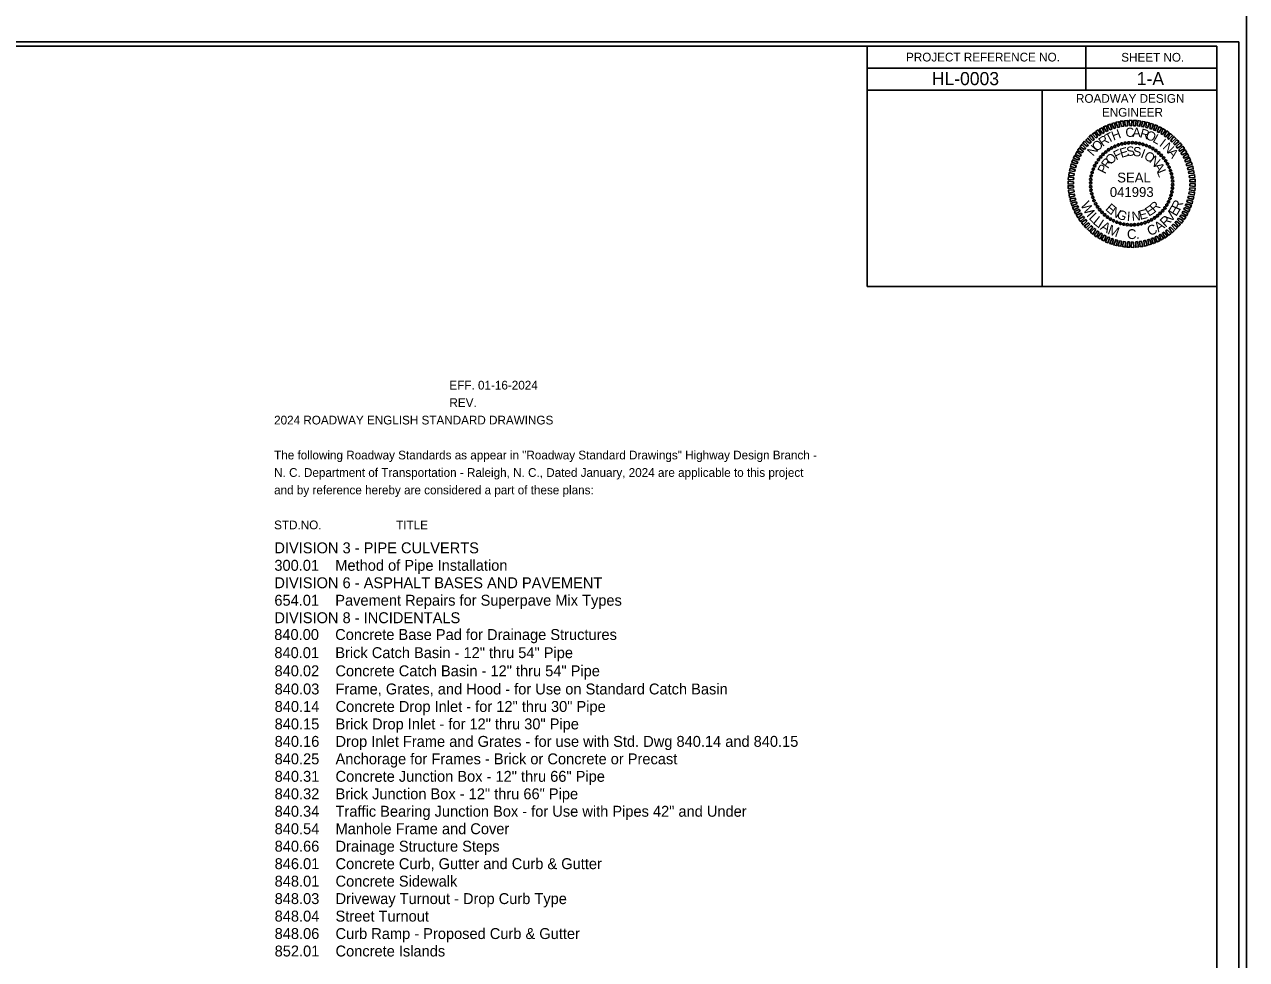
# Model space of a CAD drawing. Extents: x 925297 to 940193, y 663541 to 689899.
# Drawn here: x 933170 to 938765, y 676737 to 681019 of the extents above; entities that cross this region are included whole.
import ezdxf

# ---------------------------------------------------------------- set-up
doc = ezdxf.new("R2010")
doc.units = 0
for name, color, linetype in [('Default', 7, 'Continuous'), ('Sheet Data Field CELL', 7, 'Continuous'), ('Sheet Plan CELL', 7, 'Continuous'), ('Sheet Plot Border Inside CELL', 7, 'Continuous'), ('Sheet Plot Border Outside CELL', 7, 'Continuous')]:
    doc.layers.add(name, color=color, linetype=linetype)

msp = doc.modelspace()

# ---------------------------------------------------------------- linework, layer by layer
at = {"layer": 'Default'}
for p, q in [((938147.3, 680453.4), (938147.3, 680453.4)), ((938162, 680460.9), (938162, 680460.9)), ((938177, 680466.9), (938177, 680466.9)), ((938192.7, 680471.4), (938192.7, 680471.4)), ((938209.2, 680474.4), (938209.2, 680474.4)), ((938225.3, 680476.6), (938225.3, 680476.6)), ((938241.8, 680477), (938241.8, 680477)), ((938258.3, 680475.9), (938258.3, 680475.9)), ((938274.5, 680473.2), (938274.5, 680473.2)), ((938290.2, 680469.9), (938290.2, 680469.9)), ((938306, 680464.6), (938306, 680464.6)), ((938321, 680457.9), (938321, 680457.9)), ((938086.2, 680399.4), (938086.2, 680399.4)), ((938096.3, 680412.5), (938096.3, 680412.5)), ((938107.6, 680424.1), (938107.6, 680424.1)), ((938120, 680435.4), (938120, 680435.4)), ((938133.1, 680444.7), (938133.1, 680444.7)), ((938335.6, 680450.4), (938335.6, 680450.4)), ((938349.1, 680441), (938349.1, 680441)), ((938362.2, 680430.9), (938362.2, 680430.9)), ((938373.8, 680419.6), (938373.8, 680419.6)), ((938385.1, 680407.2), (938385.1, 680407.2)), ((938062.6, 680356.2), (938062.6, 680356.2)), ((938069.3, 680371.2), (938069.3, 680371.2)), ((938076.8, 680385.9), (938076.8, 680385.9)), ((938394.5, 680394.1), (938394.5, 680394.1)), ((938403.1, 680379.9), (938403.1, 680379.9)), ((938410.6, 680365.2), (938410.6, 680365.2)), ((938416.6, 680350.2), (938416.6, 680350.2)), ((938050.2, 680292.1), (938050.2, 680292.1)), ((938051.3, 680308.6), (938051.3, 680308.6)), ((938054, 680324.7), (938054, 680324.7)), ((938057.3, 680340.5), (938057.3, 680340.5)), ((938238.5, 680288.7), (938238.5, 680288.7)), ((938421.1, 680334.5), (938421.1, 680334.5)), ((938424.1, 680318), (938424.1, 680318)), ((938426.3, 680301.9), (938426.3, 680301.9)), ((938426.7, 680285.4), (938426.7, 680285.4)), ((938050.6, 680275.6), (938050.6, 680275.6)), ((938052.8, 680259.5), (938052.8, 680259.5)), ((938055.8, 680243), (938055.8, 680243)), ((938419.6, 680237), (938419.6, 680237)), ((938423, 680252.7), (938423, 680252.7)), ((938425.6, 680268.9), (938425.6, 680268.9)), ((938060.3, 680227.2), (938060.3, 680227.2)), ((938066.3, 680212.2), (938066.3, 680212.2)), ((938073.8, 680197.6), (938073.8, 680197.6)), ((938082.5, 680183.4), (938082.5, 680183.4)), ((938390.7, 680178.1), (938390.7, 680178.1)), ((938400.1, 680191.6), (938400.1, 680191.6)), ((938407.6, 680206.2), (938407.6, 680206.2)), ((938414.3, 680221.2), (938414.3, 680221.2)), ((938091.8, 680170.2), (938091.8, 680170.2)), ((938103.1, 680157.9), (938103.1, 680157.9)), ((938114.7, 680146.6), (938114.7, 680146.6)), ((938127.8, 680136.5), (938127.8, 680136.5)), ((938141.3, 680127.1), (938141.3, 680127.1)), ((938156, 680119.6), (938156, 680119.6)), ((938329.6, 680124.1), (938329.6, 680124.1)), ((938343.8, 680132.7), (938343.8, 680132.7)), ((938357, 680142.1), (938357, 680142.1)), ((938369.3, 680153.4), (938369.3, 680153.4)), ((938380.6, 680165), (938380.6, 680165)), ((938171, 680112.9), (938171, 680112.9)), ((938186.7, 680107.6), (938186.7, 680107.6)), ((938202.5, 680104.2), (938202.5, 680104.2)), ((938218.6, 680101.6), (938218.6, 680101.6)), ((938235.1, 680100.5), (938235.1, 680100.5)), ((938251.6, 680100.9), (938251.6, 680100.9)), ((938267.7, 680103.1), (938267.7, 680103.1)), ((938284.2, 680106.1), (938284.2, 680106.1)), ((938300, 680110.6), (938300, 680110.6)), ((938315, 680116.6), (938315, 680116.6))]:
    msp.add_line(p, q, dxfattribs=at)
for points in [[(938156.7, 680542.2), (938148.1, 680564.7), (938159.7, 680568.1), (938164.6, 680544.9)], [(938174.7, 680547.1), (938166.8, 680570.7), (938179.6, 680573.4), (938182.6, 680549)], [(938192.7, 680551.2), (938186.7, 680575.2), (938199.1, 680576.4), (938201.7, 680552.4)], [(938210.7, 680553.5), (938206.6, 680577.5), (938219.3, 680579), (938219.7, 680554.6)], [(938229.5, 680555.4), (938227.6, 680579.7), (938240, 680579.4), (938238.5, 680555)], [(938247.5, 680555), (938247.5, 680579.4), (938259.8, 680579), (938256.5, 680554.6)], [(938266.2, 680553.9), (938267.7, 680578.2), (938280.1, 680576), (938275.2, 680552.4)], [(938284.2, 680550.9), (938287.6, 680574.9), (938300, 680573), (938293.2, 680549.7)], [(938303.3, 680546.7), (938307.1, 680571.1), (938319.8, 680568.1), (938311.2, 680544.9)], [(938321.3, 680541.9), (938327, 680565.1), (938338.6, 680561.4), (938329.2, 680539.2)], [(938060, 680487.1), (938043.5, 680503.6), (938052.5, 680512.6), (938067.1, 680492.4)], [(938075, 680498.7), (938058.8, 680516.7), (938069, 680524.6), (938082.1, 680503.6)], [(938089.2, 680510), (938075.3, 680529.1), (938085.1, 680536.2), (938097.5, 680514.5)], [(938105.7, 680519.4), (938091.8, 680539.6), (938103.5, 680545.6), (938112.8, 680523.9)], [(938121.8, 680528.4), (938109.8, 680549.4), (938121.5, 680554.6), (938130.1, 680531.7)], [(938138.3, 680536.2), (938128.6, 680558), (938139.8, 680562.5), (938147.7, 680538.5)], [(938338.2, 680535.1), (938346.8, 680558.7), (938357.3, 680554.2), (938346.8, 680532.5)], [(938355.1, 680528), (938364.5, 680550.1), (938376.1, 680544.9), (938363.3, 680523.9)], [(938372.3, 680519.4), (938382.5, 680540.7), (938393.7, 680534.4), (938379.5, 680514.9)], [(938387, 680509.2), (938400.1, 680531), (938409.8, 680523.1), (938395.2, 680504.7)], [(938402.3, 680498), (938416.2, 680518.6), (938426, 680510.4), (938409.5, 680492.7)], [(938023.2, 680445.5), (938003, 680458.2), (938010.1, 680469.1), (938028.1, 680452.6)], [(938034.5, 680459.7), (938015, 680474.4), (938023.2, 680484.1), (938039.7, 680466.5)], [(938047.6, 680474), (938028.5, 680489.4), (938037.8, 680498), (938053.6, 680480)], [(938416.6, 680486.4), (938432, 680505.9), (938441, 680496.9), (938423.7, 680480.7)], [(938430.1, 680473.2), (938446.2, 680490.9), (938455.2, 680481.9), (938435.7, 680467.2)], [(938443.2, 680459.7), (938460.5, 680476.6), (938468.3, 680466.5), (938448.5, 680452.2)], [(938454.5, 680445.1), (938472.8, 680460.9), (938480, 680450), (938459, 680438)], [(937988, 680380.6), (937964.7, 680387.4), (937969.6, 680399), (937992.1, 680388.5)], [(937995.5, 680397.1), (937972.2, 680405.7), (937977.8, 680417.4), (937999.2, 680405.4)], [(938003, 680414.4), (937981.6, 680423.7), (937987.2, 680435.4), (938007.5, 680421.5)], [(938012, 680430.5), (937991, 680441.7), (937998.5, 680452.2), (938018, 680437.2)], [(938464.2, 680429.7), (938484.1, 680444), (938491.2, 680432.7), (938469.5, 680422.2)], [(938474, 680413.2), (938495, 680426.4), (938499.8, 680414.7), (938478.5, 680406.1)], [(938481.5, 680397.1), (938503.6, 680408.4), (938508.5, 680396.4), (938485.2, 680388.9)], [(937977.5, 680344.6), (937954.2, 680347.6), (937956.8, 680360.4), (937980.5, 680352.5)], [(937982.3, 680362.6), (937959.1, 680367.5), (937961.7, 680379.9), (937985.3, 680370.5)], [(938488.2, 680379.5), (938511.1, 680389.2), (938515.2, 680377.6), (938492, 680371.6)], [(938494.2, 680361.5), (938518.2, 680370.1), (938520.5, 680357.7), (938496.8, 680353.6)], [(938498.7, 680343.5), (938522.3, 680350.6), (938524.6, 680337.9), (938501, 680335.6)], [(937972.2, 680288.7), (937947.8, 680287.6), (937947.8, 680300.4), (937972.2, 680297.7)], [(937972.6, 680307.5), (937948.2, 680308.2), (937949, 680320.6), (937973.3, 680316.5)], [(937974.5, 680325.5), (937950.5, 680327.7), (937952, 680340.5), (937976.3, 680334.5)], [(938502.1, 680325.5), (938526.5, 680330.7), (938527.6, 680318), (938503.6, 680316.5)], [(938504.3, 680307.5), (938528.7, 680310.5), (938529.5, 680297.7), (938505.1, 680298.5)], [(938504.7, 680288.7), (938529.1, 680289.9), (938529.1, 680277.1), (938504.7, 680279.7)], [(937972.6, 680270), (937948.2, 680267), (937947.5, 680279.7), (937971.8, 680279)], [(937974.8, 680252), (937950.5, 680246.7), (937949.3, 680259.5), (937973.3, 680261)], [(937978.2, 680234), (937954.6, 680226.9), (937952.3, 680239.6), (937976, 680241.9)], [(938499.5, 680232.9), (938522.7, 680229.9), (938520.1, 680217.1), (938496.5, 680225)], [(938502.5, 680252), (938526.5, 680249.7), (938525, 680237), (938500.6, 680243)], [(938504.3, 680270), (938528.7, 680269.2), (938528, 680256.9), (938503.6, 680261)], [(937982.7, 680216), (937958.7, 680207.4), (937956.5, 680219.7), (937980.1, 680223.9)], [(937988.7, 680198), (937965.8, 680188.2), (937961.7, 680199.9), (937985, 680205.9)], [(937995.5, 680180.4), (937973.3, 680169.1), (937968.5, 680181.1), (937991.7, 680188.6)], [(938481.5, 680180.4), (938504.7, 680171.7), (938499.1, 680160.1), (938477.7, 680172.1)], [(938489, 680196.9), (938512.2, 680190.1), (938507.3, 680178.5), (938484.8, 680189)], [(938494.6, 680214.9), (938517.8, 680210), (938515.2, 680197.6), (938491.6, 680207)], [(938003, 680164.2), (937982, 680151.1), (937977.1, 680162.7), (937998.5, 680171.4)], [(938012.7, 680147.7), (937992.8, 680133.5), (937985.7, 680144.7), (938007.5, 680155.2)], [(938022.5, 680132.4), (938004.1, 680116.6), (937997, 680127.5), (938018, 680139.5)], [(938033.7, 680117.7), (938016.5, 680100.9), (938008.6, 680111), (938028.5, 680125.2)], [(938442.5, 680117.7), (938462, 680103.1), (938453.7, 680093.4), (938437.2, 680111)], [(938453.7, 680132), (938474, 680119.2), (938466.8, 680108.4), (938448.8, 680124.9)], [(938465, 680147), (938486, 680135.7), (938478.5, 680125.2), (938459, 680140.2)], [(938474, 680163.1), (938495.3, 680153.7), (938489.7, 680142.1), (938469.5, 680156)], [(938046.8, 680104.2), (938030.7, 680086.6), (938021.7, 680095.6), (938041.2, 680110.2)], [(938060.3, 680091.1), (938045, 680071.6), (938036, 680080.6), (938053.2, 680096.7)], [(938074.6, 680079.5), (938060.7, 680058.9), (938051, 680067.1), (938067.5, 680084.7)], [(938090, 680068.2), (938076.8, 680046.5), (938067.1, 680054.4), (938081.7, 680072.7)], [(938104.6, 680058.1), (938094.5, 680036.7), (938083.2, 680043.1), (938097.5, 680062.6)], [(938387.7, 680067.5), (938401.6, 680048.4), (938391.8, 680041.2), (938379.5, 680063)], [(938402, 680078.7), (938418.1, 680060.7), (938408, 680052.9), (938394.8, 680073.9)], [(938417, 680090.4), (938433.5, 680073.9), (938424.5, 680064.9), (938409.8, 680085.1)], [(938429.3, 680103.5), (938448.5, 680088.1), (938439.1, 680079.5), (938423.3, 680097.5)], [(938121.8, 680049.5), (938112.5, 680027.4), (938100.8, 680032.6), (938113.6, 680053.6)], [(938138.7, 680042.4), (938130.1, 680018.7), (938119.6, 680023.2), (938130.1, 680045)], [(938155.6, 680035.6), (938150, 680012.4), (938138.3, 680016.1), (938147.7, 680038.2)], [(938173.6, 680030.7), (938169.8, 680006.4), (938157.1, 680009.4), (938165.7, 680032.6)], [(938192.7, 680026.6), (938189.3, 680002.6), (938177, 680004.5), (938183.7, 680027.7)], [(938210.7, 680023.6), (938209.2, 679999.2), (938196.8, 680001.5), (938201.7, 680025.1)], [(938229.5, 680022.5), (938229.5, 679998.1), (938217.1, 679998.5), (938220.5, 680022.9)], [(938247.5, 680022.1), (938249.3, 679997.7), (938237, 679998.1), (938238.5, 680022.5)], [(938266.2, 680024), (938270.3, 680000), (938257.6, 679998.5), (938257.2, 680022.9)], [(938284.2, 680026.2), (938290.2, 680002.2), (938277.8, 680001.1), (938275.2, 680025.1)], [(938302.2, 680030.4), (938310.1, 680006.7), (938297.3, 680004.1), (938294.3, 680028.5)], [(938320.2, 680035.2), (938328.8, 680012.7), (938317.2, 680009.4), (938312.3, 680032.6)], [(938338.6, 680041.2), (938348.3, 680019.5), (938337.1, 680015), (938329.2, 680039)], [(938355.1, 680049.1), (938367.1, 680028.1), (938355.5, 680022.9), (938346.8, 680045.7)], [(938371.2, 680058.1), (938385.1, 680037.9), (938373.5, 680031.9), (938364.1, 680053.6)]]:
    msp.add_lwpolyline(points, close=True, dxfattribs=at)
for centre, major_axis in [((938147.3, 680453.3), (-2.62, 4.72)), ((938162, 680460.6), (-2.2, 4.93)), ((938177.2, 680466.6), (-1.76, 5.11)), ((938193, 680471.3), (-1.31, 5.24)), ((938209, 680474.5), (-0.84, 5.33)), ((938225.4, 680476.4), (-0.38, 5.39)), ((938241.8, 680476.8), (0.09, 5.4)), ((938258.1, 680475.8), (0.56, 5.37)), ((938274.4, 680473.4), (1.03, 5.3)), ((938290.3, 680469.6), (1.49, 5.19)), ((938305.9, 680464.3), (1.94, 5.04)), ((938320.9, 680457.8), (2.37, 4.85)), ((938335.4, 680450), (2.78, 4.63)), ((938086.3, 680399.3), (-4.37, 3.17)), ((938096.5, 680412.1), (-4.08, 3.54)), ((938107.8, 680424), (-3.75, 3.88)), ((938120.1, 680434.9), (-3.4, 4.2)), ((938133.3, 680444.7), (-3.02, 4.48)), ((938349, 680440.9), (3.17, 4.37)), ((938361.9, 680430.7), (3.54, 4.08)), ((938373.8, 680419.4), (3.88, 3.75)), ((938384.7, 680407.1), (4.2, 3.4)), ((938394.4, 680393.9), (4.48, 3.02)), ((938057.7, 680340.6), (-5.19, 1.49)), ((938062.9, 680356.1), (-5.04, 1.94)), ((938069.4, 680371.2), (-4.85, 2.37)), ((938077.2, 680385.6), (-4.63, 2.78)), ((938403, 680379.9), (4.72, 2.62)), ((938410.3, 680365.2), (4.93, 2.2)), ((938416.3, 680350), (5.11, 1.76)), ((938050.4, 680292), (-5.4, 0.09)), ((938051.4, 680308.4), (-5.37, 0.56)), ((938053.8, 680324.6), (-5.3, 1.03)), ((938421, 680334.2), (5.24, 1.31)), ((938424.3, 680318.2), (5.33, 0.84)), ((938426.1, 680301.9), (5.39, 0.38)), ((938426.5, 680285.5), (5.4, -0.09)), ((938050.8, 680275.6), (-5.39, -0.38)), ((938052.7, 680259.3), (-5.33, -0.84)), ((938056, 680243.2), (-5.24, -1.31)), ((938060.6, 680227.5), (-5.11, -1.76)), ((938419.3, 680236.9), (5.19, -1.49)), ((938423.1, 680252.8), (5.3, -1.03)), ((938425.5, 680269.1), (5.37, -0.56)), ((938066.6, 680212.2), (-4.93, -2.2)), ((938074, 680197.5), (-4.72, -2.62)), ((938082.5, 680183.6), (-4.48, -3.02)), ((938092.3, 680170.4), (-4.2, -3.4)), ((938390.6, 680178.2), (4.37, -3.17)), ((938399.7, 680191.9), (4.63, -2.78)), ((938407.5, 680206.3), (4.85, -2.37)), ((938414.1, 680221.3), (5.04, -1.94)), ((938103.2, 680158.1), (-3.88, -3.75)), ((938115.1, 680146.8), (-3.54, -4.08)), ((938127.9, 680136.6), (-3.17, -4.37)), ((938141.6, 680127.5), (-2.78, -4.63)), ((938156, 680119.7), (-2.37, -4.85)), ((938171.1, 680113.1), (-1.94, -5.04)), ((938299.7, 680110.9), (1.76, -5.11)), ((938315, 680116.9), (2.2, -4.93)), ((938329.7, 680124.2), (2.62, -4.72)), ((938343.7, 680132.8), (3.02, -4.48)), ((938356.8, 680142.6), (3.4, -4.2)), ((938369.1, 680153.4), (3.75, -3.88)), ((938380.4, 680165.3), (4.08, -3.54)), ((938186.6, 680107.9), (-1.49, -5.19)), ((938202.6, 680104.1), (-1.03, -5.3)), ((938218.8, 680101.7), (-0.56, -5.37)), ((938235.2, 680100.7), (-0.09, -5.4)), ((938251.6, 680101.1), (0.38, -5.39)), ((938267.9, 680103), (0.84, -5.33)), ((938284, 680106.2), (1.31, -5.24))]:
    msp.add_ellipse(centre, major_axis=major_axis, ratio=0.999708, dxfattribs=at)
at = {"layer": 'Sheet Plan CELL'}
for p, q in [((937028.3, 680918.7), (938628.7, 680918.7)), ((937028.3, 679818.3), (937028.3, 680918.7)), ((938028.7, 680918.3), (938028.7, 680718.3)), ((938628.7, 680918.7), (938628.7, 680718.3)), ((937028.3, 680818.3), (938628.7, 680818.3)), ((938628.7, 680718.3), (937028.3, 680718.3)), ((938628.7, 680718.3), (937028.3, 680718.3)), ((937828.7, 680718.3), (938628.7, 680718.3)), ((937828.7, 679818.3), (937828.7, 680718.3)), ((938628.7, 680718.3), (938628.7, 679818.3)), ((938628.7, 679818.3), (937028.3, 679818.3)), ((938628.7, 679818.3), (937028.3, 679818.3))]:
    msp.add_line(p, q, dxfattribs=at)
msp.add_lwpolyline([(938628.7, 680918.7), (926628.7, 680918.7), (926628.7, 672518.7), (938628.7, 672518.7)], close=True, dxfattribs=at)
at = {"layer": 'Sheet Plot Border Inside CELL'}
msp.add_lwpolyline([(925400.7, 672498.7), (938728.7, 672498.7), (938728.7, 680938.7), (925400.7, 680938.7)], close=True, dxfattribs=at)
at = {"layer": 'Sheet Plot Border Outside CELL'}
msp.add_lwpolyline([(925296.7, 672338.7), (938764.7, 672338.7), (938764.7, 681098.7), (925296.7, 681098.7)], close=True, dxfattribs=at)

# ---------------------------------------------------------------- texts
at = {"layer": 'Default'}
for s, height, rotation, p in [('R', 42.3, 35.0205, (938105.7, 680457.5)), ('T', 42.3, 27.8198, (938131.2, 680474)), ('H', 42.3, 20.6195, (938155.6, 680486.4)), ('C', 42.3, 6.2199, (938212.6, 680501.4)), ('A', 42.3, 359.0203, (938242.2, 680503.6)), ('R', 42.3, 344.6211, (938273.7, 680502.1)), ('O', 42.3, 337.4212, (938298.8, 680496.5)), ('L', 42.3, 330.2209, (938331.8, 680482.6)), ('N', 42.3, 49.4235, (938062.6, 680412.5)), ('O', 42.3, 42.2217, (938079.8, 680434.2)), ('E', 42.3, 16.6111, (938191.6, 680407.2)), ('S', 42.3, 7.2556, (938217.5, 680415.1)), ('S', 42.3, 357.9004, (938244.5, 680415.5)), ('I', 42.3, 323.0201, (938362.2, 680464.6)), ('N', 42.3, 315.8189, (938378.3, 680453)), ('R', 42.3, 54.0397, (938129.7, 680355.5)), ('O', 42.3, 44.6812, (938142.8, 680373.9)), ('F', 42.3, 25.967, (938167.6, 680396)), ('I', 42.3, 339.1896, (938276.7, 680410.2)), ('O', 42.3, 329.8335, (938291.7, 680405)), ('N', 42.3, 320.4766, (938316.8, 680390)), ('A', 42.3, 308.6172, (938400.5, 680430.9)), ('P', 42.3, 63.3989, (938117.7, 680331.5)), ('SEAL', 44.99, 360, (938172.5, 680295.1)), ('A', 42.3, 301.7603, (938338.2, 680370.5)), ('L', 42.3, 292.4008, (938352.8, 680344.6)), ('W', 45, 298.3574, (938002.9, 680193)), ('E', 42.3, 318.2769, (938115.5, 680171.4)), ('N', 42.3, 327.634, (938138, 680151.1)), ('E', 42.3, 14.4118, (938277.8, 680123.4)), ('E', 42.3, 33.1241, (938317.6, 680138)), ('R', 42.3, 42.4814, (938344.2, 680155.6)), ('E', 45, 59.5871, (938442.5, 680136.9)), ('R', 45, 66.6964, (938459.7, 680163.4)), ('I', 45, 310.8915, (938029.3, 680144.2)), ('L', 45, 314.6934, (938039.4, 680130.6)), ('L', 45, 320.9682, (938057.8, 680109.8)), ('I', 45, 327.2429, (938078.5, 680091.1)), ('G', 42.3, 336.9902, (938166.5, 680134.2)), ('I', 42.3, 355.7012, (938215.6, 680120)), ('N', 42.3, 5.0564, (938240.7, 680118.9)), ('R', 45, 43.8538, (938393.7, 680087.3)), ('V', 45, 51.3341, (938418.6, 680109.2)), ('A', 45, 331.0449, (938091.9, 680081)), ('M', 45, 339.8852, (938125.6, 680060.9)), ('C', 45, 1.6151, (938218, 680035.3)), ('C', 45, 25.4313, (938322, 680048.6)), ('A', 45, 35.0135, (938360.9, 680065.9)), ('.', 45, 11.1972, (938260.4, 680035.4))]:
    msp.add_text(s, height=height, rotation=rotation, dxfattribs=at).set_placement(p)
for s, height, p in [('041993', 44.99, (938138.7, 680228.7)), ('                                                      EFF. 01-16-2024', 40, (934313.2, 679346.9)), ('                                                      REV. ', 40, (934313.2, 679266.9)), ('2024 ROADWAY ENGLISH STANDARD DRAWINGS', 40, (934313.2, 679186.9)), ('The following Roadway Standards as appear in "Roadway Standard Drawings" Highway Design Branch -', 40, (934313.2, 679026.9)), ('N. C. Department of Transportation - Raleigh, N. C., Dated January, 2024 are applicable to this project', 40, (934313.2, 678946.9)), ('and by reference hereby are considered a part of these plans:', 40, (934313.2, 678866.9)), ('STD.NO.                       TITLE', 40, (934313.2, 678706.9)), ('DIVISION 3 - PIPE CULVERTS', 50, (934314.4, 678596.9)), ('300.01    Method of Pipe Installation ', 50, (934314.4, 678516.9)), ('DIVISION 6 - ASPHALT BASES AND PAVEMENT', 50, (934314.4, 678436.9)), ('654.01    Pavement Repairs for Superpave Mix Types ', 50, (934314.4, 678356.9)), ('DIVISION 8 - INCIDENTALS', 50, (934314.4, 678276.9)), ('840.00    Concrete Base Pad for Drainage Structures', 50, (934313.9, 678200)), ('840.01    Brick Catch Basin - 12" thru 54" Pipe', 50, (934314.4, 678116.9)), ('840.02    Concrete Catch Basin - 12" thru 54" Pipe', 50, (934315, 678033.7)), ('840.03    Frame, Grates, and Hood - for Use on Standard Catch Basin', 50, (934315.6, 677950.6)), ('840.14    Concrete Drop Inlet - for 12" thru 30" Pipe', 50, (934315.6, 677870.6)), ('840.15    Brick Drop Inlet - for 12" thru 30" Pipe', 50, (934315.6, 677790.6)), ('840.16    Drop Inlet Frame and Grates - for use with Std. Dwg 840.14 and 840.15', 50, (934315.6, 677710.6)), ('840.25    Anchorage for Frames - Brick or Concrete or Precast', 50, (934315.6, 677630.6)), ('840.31    Concrete Junction Box - 12" thru 66" Pipe', 50, (934315.6, 677550.6)), ('840.32    Brick Junction Box - 12" thru 66" Pipe', 50, (934315.6, 677470.6)), ('840.34    Traffic Bearing Junction Box - for Use with Pipes 42" and Under', 50, (934315.6, 677390.6)), ('840.54    Manhole Frame and Cover', 50, (934315.6, 677310.6)), ('840.66    Drainage Structure Steps', 50, (934315.6, 677230.6)), ('846.01    Concrete Curb, Gutter and Curb & Gutter', 50, (934315.6, 677150.6)), ('848.01    Concrete Sidewalk', 50, (934315.6, 677070.6)), ('848.03    Driveway Turnout - Drop Curb Type', 50, (934315.6, 676990.6)), ('848.04    Street Turnout', 50, (934315.6, 676910.6)), ('848.06    Curb Ramp - Proposed Curb & Gutter', 50, (934315.6, 676830.6)), ('852.01    Concrete Islands', 50, (934315.6, 676750.6))]:
    msp.add_text(s, height=height, dxfattribs=at).set_placement(p)
at = {"layer": 'Sheet Data Field CELL'}
for s, p in [('HL-0003', (937323.9, 680740.7)), ('1-A', (938262.1, 680740.7))]:
    msp.add_text(s, height=60, dxfattribs=at).set_placement(p)
at = {"layer": 'Sheet Plan CELL'}
for s, height, p in [('PROJECT REFERENCE NO.', 40.001, (937205.9, 680849.1)), ('SHEET NO.', 40, (938191.1, 680848.3)), ('ROADWAY DESIGN', 40.001, (937983.9, 680659.9)), ('ENGINEER', 40, (938102.7, 680596.3))]:
    msp.add_text(s, height=height, dxfattribs=at).set_placement(p)

doc.saveas('drawing.dxf')
